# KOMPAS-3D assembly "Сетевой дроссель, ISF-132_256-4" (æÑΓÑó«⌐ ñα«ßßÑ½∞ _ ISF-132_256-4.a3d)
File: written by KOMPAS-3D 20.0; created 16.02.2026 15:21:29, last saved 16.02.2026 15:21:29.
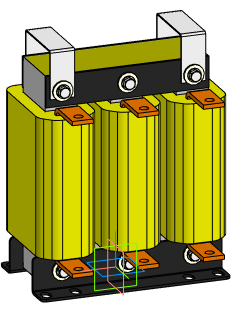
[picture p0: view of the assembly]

Document properties: Автор: admin; Полное имя файла: P:\INSTART\Технический отдел\ОР\Прочие задачи\КД на номенклатурный ряд\КД на типоразмеры дросселей\Сетевые дроссели ISF\ISF-4\Тип 1\ISF-132_256-4\0723\Новая папка\Сетевой дроссель _ ISF-132_256-4.a3d

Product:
- Part/product: Сетевой дроссель  | designation ISF-132_256-4
  - Component [detail]: Скоба такелажная  | designation ISF-132_256-4  | qty 2  | source file: Скоба такелажная.m3d
  - Component [assembly]: Гайка М8  | designation DIN 934  | qty 6  | source file: Гайка М8.a3d
  - Component [assembly]: Шайба пружинная D8  | designation DIN 127 (A)  | qty 6  | source file: Шайба пружинная D8.a3d
  - Component [assembly]: Болт М8х100  | designation ГОСТ 15591-70  | qty 6  | source file: Болт М8х100.a3d
  - Component [assembly]: Шайба плоская D8  | designation DIN 125 (A)  | qty 12  | source file: Шайба плоская D8.a3d
  - Component [assembly]: Шайба плоская D8 полиамидная  | qty 12  | source file: Шайба плоская D8 полиамидная.a3d
  - Component [detail]: Пластина поджимная  | designation ISF-132_256-4  | qty 2  | source file: Пластина поджимная.m3d
  - Component [detail]: Клемма  | designation ISF-132_256-4  | qty 6  | source file: Клемма.m3d
  - Component [detail]: Катушка  | designation ISF-132_256-4  | qty 3  | source file: Катушка.m3d
  - Component [detail]: Лапа  | designation ISF-132_256-4  | qty 2  | source file: Лапа.m3d
  - Component [detail]: Сердечник  | designation ISF-132_256-4  | source file: Сердечник.m3d

Expressions: ISF-132_256-4
Referenced files in P:\INSTART\Технический отдел\ОР\Прочие задачи\КД на номенклатурный ряд\КД на типоразмеры дросселей\Сетевые дроссели ISF\ISF-4\Тип 1\ISF-132_256-4\0723\Новая папка\: Сердечник.m3d, Лапа.m3d, Катушка.m3d, Клемма.m3d, Пластина поджимная.m3d, Шайба плоская D8 полиамидная.a3d, Шайба плоская D8.a3d, Болт М8х100.a3d, Шайба пружинная D8.a3d, Гайка М8.a3d, Скоба такелажная.m3d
